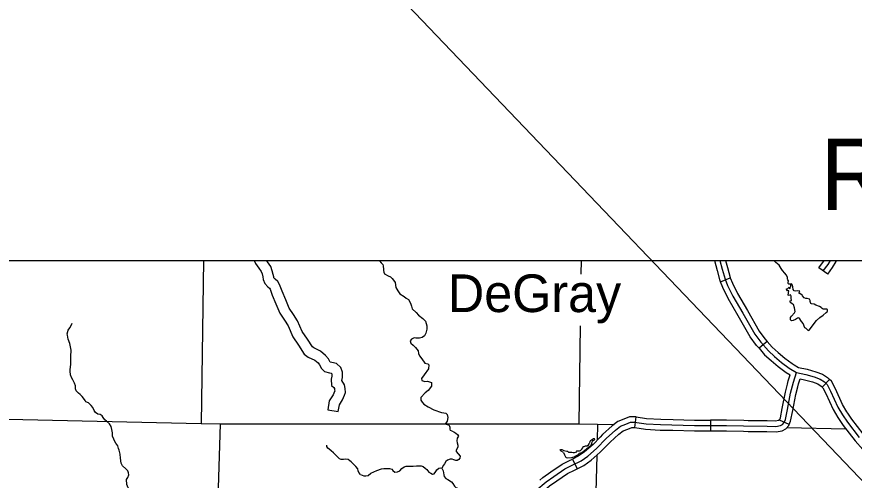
# Model space of a CAD drawing. Extents: x 813775 to 1157140, y 1757555 to 1979907.
# Drawn here: x 927663 to 951173, y 1874542 to 1887546 of the extents above; entities that cross this region are included whole.
import ezdxf

# ---------------------------------------------------------------- set-up
doc = ezdxf.new("R2010")
doc.units = 0
for name, color, linetype in [('Level 24', 7, 'Continuous'), ('Level 31', 7, 'Continuous'), ('Level 32', 7, 'Continuous'), ('Level 35', 7, 'Continuous'), ('Level 4', 7, 'Continuous'), ('Level 45', 7, 'Continuous'), ('Level 46', 7, 'Continuous'), ('Level 5', 7, 'Continuous'), ('R_Draft', 7, 'Continuous')]:
    doc.layers.add(name, color=color, linetype=linetype)

msp = doc.modelspace()

# ---------------------------------------------------------------- linework, layer by layer
at = {"layer": 'Level 31'}
for p, q in [((947416, 1880105), (947694, 1880218)), ((948729, 1878439), (948501, 1878244)), ((950480, 1877372), (950274, 1877154)), ((950994, 1876420), (950994, 1876420)), ((945009, 1876020), (945050, 1876317)), ((947138, 1876229), (947138, 1875929)), ((949348, 1876107), (949074, 1876229)), ((949074, 1876229), (949074, 1876229)), ((943263, 1875135), (943392, 1874864))]:
    msp.add_line(p, q, dxfattribs=at)
for points in [[(947249, 1880709), (947321, 1880429), (947404, 1880134), (947416, 1880105)], [(947404, 1880709), (947466, 1880468), (947546, 1880183), (947617, 1880009), (947764, 1879711), (948043, 1879226), (948381, 1878644), (948550, 1878418), (948763, 1878169), (948936, 1878013), (949131, 1877849), (949349, 1877689), (949555, 1877567)], [(947559, 1880709), (947611, 1880507), (947688, 1880232), (947694, 1880218)], [(947694, 1880218), (947754, 1880070), (947896, 1879781), (948173, 1879301)], [(947913, 1879151), (947631, 1879640), (947480, 1879947), (947416, 1880105)], [(948173, 1879301), (948173, 1879301), (948506, 1878727), (948667, 1878511), (948729, 1878439)], [(948501, 1878244), (948432, 1878324), (948255, 1878561), (947914, 1879151), (947913, 1879151)], [(948729, 1878439), (948870, 1878274), (949034, 1878126), (949224, 1877967), (949432, 1877814), (949486, 1877782)], [(948501, 1878244), (948655, 1878064), (948837, 1877900), (949038, 1877731), (949266, 1877563), (949375, 1877499)], [(949486, 1877782), (949611, 1877708), (949851, 1877654), (950097, 1877585), (950281, 1877515), (950426, 1877423), (950480, 1877372)], [(949555, 1877567), (949814, 1877509), (950049, 1877442), (950214, 1877380), (950334, 1877304), (950414, 1877229), (950507, 1877042), (950711, 1876593), (950840, 1876380), (950986, 1876167), (951311, 1875744)], [(949296, 1877233), (949322, 1877333), (949375, 1877499)], [(949587, 1877159), (949610, 1877250), (949656, 1877391)], [(949656, 1877391), (949777, 1877363), (950002, 1877299), (950147, 1877245), (950241, 1877185), (950274, 1877154)], [(950994, 1876420), (950966, 1876461), (950844, 1876663), (950642, 1877107), (950536, 1877319), (950480, 1877372)], [(949074, 1876229), (949100, 1876288), (949150, 1876551), (949240, 1877014), (949296, 1877233)], [(949348, 1876107), (949388, 1876198), (949445, 1876495), (949533, 1876948), (949587, 1877159)], [(950274, 1877154), (950291, 1877138), (950371, 1876977), (950578, 1876523), (950714, 1876299), (950747, 1876250)], [(951636, 1875608), (951426, 1875840), (951108, 1876255), (950994, 1876420)], [(945050, 1876317), (945016, 1876322), (944860, 1876316), (944708, 1876253), (944540, 1876189), (944375, 1876065), (944109, 1875822), (944042, 1875753)], [(945050, 1876317), (945343, 1876277), (945739, 1876251), (946085, 1876243)], [(946085, 1876243), (946693, 1876229), (947138, 1876229)], [(948196, 1876213), (948071, 1876215), (947590, 1876229), (947138, 1876229)], [(949074, 1876229), (949081, 1876246), (949060, 1876223), (949050, 1876217), (948962, 1876202), (948727, 1876206), (948196, 1876213)], [(950747, 1876250), (950865, 1876078), (951195, 1875648), (951413, 1875407)], [(944258, 1875544), (944318, 1875607), (944567, 1875834), (944686, 1875924), (944819, 1875975), (944925, 1876019), (945001, 1876021), (945009, 1876020)], [(945009, 1876020), (945313, 1875978), (945725, 1875951), (946078, 1875943)], [(946078, 1875943), (946689, 1875929), (947138, 1875929)], [(947138, 1875929), (947586, 1875929), (948064, 1875915), (948191, 1875913)], [(948191, 1875913), (948722, 1875906), (948985, 1875902), (949154, 1875931), (949250, 1875987), (949336, 1876079), (949348, 1876107)], [(944042, 1875753), (943840, 1875543), (943601, 1875339), (943426, 1875213), (943263, 1875135)], [(943392, 1874864), (943580, 1874953), (943787, 1875103), (944045, 1875325), (944258, 1875544)], [(942344, 1874542), (942430, 1874617), (942655, 1874773), (942974, 1874992), (943184, 1875098), (943263, 1875135)], [(942542, 1874316), (942615, 1874380), (942826, 1874526), (943127, 1874734), (943316, 1874828), (943392, 1874864)]]:
    msp.add_lwpolyline(points, dxfattribs=at)
at = {"layer": 'Level 32'}
msp.add_line((950427, 1880327), (950183, 1880503), dxfattribs=at)
for points in [[(950183, 1880503), (950313, 1880682), (950331, 1880709)], [(950305, 1880415), (950437, 1880597), (950510, 1880709)], [(950427, 1880327), (950560, 1880512), (950667, 1880675), (950678, 1880709)]]:
    msp.add_lwpolyline(points, dxfattribs=at)
at = {"layer": 'Level 35'}
for points in [[(937842, 1880709), (937850, 1880694), (937895, 1880644), (937937, 1880595), (937947, 1880558), (937955, 1880459), (937960, 1880423), (937963, 1880381), (937989, 1880329), (938090, 1880276), (938150, 1880245), (938200, 1880198), (938239, 1880157), (938288, 1880086), (938304, 1879951), (938356, 1879857), (938419, 1879771), (938539, 1879695), (938591, 1879650), (938659, 1879609), (938718, 1879512), (938742, 1879429), (938760, 1879350), (938875, 1879251), (938945, 1879173), (939058, 1879076), (939133, 1879003), (939170, 1878878), (939175, 1878776), (939144, 1878671), (939107, 1878595), (939042, 1878548), (938964, 1878530), (938870, 1878532), (938818, 1878535), (938742, 1878503), (938711, 1878449), (938721, 1878389), (938789, 1878331), (938852, 1878266), (938927, 1878169), (938943, 1878096), (938971, 1878031), (939031, 1877947), (939122, 1877824), (939207, 1877806), (939232, 1877782), (939224, 1877671), (939096, 1877503), (939028, 1877398), (939036, 1877336), (939120, 1877309), (939193, 1877320), (939305, 1877286), (939310, 1877177), (939211, 1877064), (939127, 1876991), (939010, 1876863), (939002, 1876787), (939041, 1876735), (939091, 1876675), (939209, 1876605), (939370, 1876521), (939589, 1876443), (939655, 1876435), (939704, 1876419), (939746, 1876389), (939764, 1876306), (939746, 1876201), (939709, 1876144), (939710, 1876142)], [(949298, 1880236), (949262, 1880307), (949220, 1880354), (949157, 1880427), (949118, 1880484), (949064, 1880578), (948975, 1880648), (948914, 1880709)], [(949395, 1880046), (949337, 1880045), (949322, 1880066), (949319, 1880092), (949324, 1880132), (949311, 1880160), (949296, 1880184), (949296, 1880207), (949298, 1880236)], [(949620, 1879101), (949577, 1879093), (949525, 1879056), (949455, 1879020), (949416, 1879012), (949384, 1879040), (949379, 1879106), (949408, 1879145), (949499, 1879239), (949510, 1879278), (949494, 1879375), (949463, 1879476), (949431, 1879487), (949392, 1879516), (949369, 1879552), (949379, 1879573), (949408, 1879589), (949405, 1879651), (949403, 1879704), (949384, 1879740), (949343, 1879724), (949319, 1879732), (949319, 1879758), (949327, 1879777), (949330, 1879797), (949335, 1879855), (949298, 1879855), (949270, 1879899), (949267, 1879915), (949304, 1879923), (949350, 1879957), (949369, 1879912), (949377, 1879962), (949392, 1879980), (949395, 1880046)], [(949620, 1879101), (949685, 1878999), (949742, 1878928), (949755, 1878873), (949776, 1878824), (949815, 1878811), (949852, 1878769), (949878, 1878746), (949909, 1878748), (949948, 1878798), (950024, 1878905), (950110, 1879022), (950206, 1879106), (950303, 1879176), (950386, 1879249), (950412, 1879268), (950422, 1879296), (950420, 1879330), (950404, 1879343), (950365, 1879346), (950331, 1879343), (950297, 1879346), (950269, 1879364), (950248, 1879390), (950196, 1879414), (950096, 1879458), (950044, 1879479), (949971, 1879492), (949950, 1879503), (949937, 1879560), (949935, 1879589), (949914, 1879620), (949851, 1879643), (949812, 1879638), (949768, 1879662), (949716, 1879714), (949708, 1879743), (949684, 1879756), (949645, 1879782), (949630, 1879784), (949627, 1879813), (949648, 1879844), (949632, 1879850), (949580, 1879852), (949530, 1879842), (949489, 1879860), (949460, 1879894), (949447, 1879972), (949442, 1880019), (949410, 1880048), (949395, 1880046)], [(929150, 1878382), (929104, 1878504), (929083, 1878608), (929080, 1878653), (929102, 1878751), (929155, 1878818), (929203, 1878903), (929221, 1878945)], [(929160, 1877653), (929179, 1877787), (929184, 1877909), (929181, 1878012), (929189, 1878191), (929150, 1878382)], [(929938, 1876394), (929872, 1876446), (929835, 1876499), (929800, 1876579), (929755, 1876643), (929673, 1876714), (929601, 1876746), (929585, 1876781), (929540, 1876847), (929497, 1876895), (929442, 1876946), (929397, 1876986), (929333, 1877049), (929312, 1877105), (929314, 1877193), (929280, 1877262), (929235, 1877360), (929203, 1877427), (929171, 1877501), (929158, 1877600), (929160, 1877653)], [(930353, 1875777), (930350, 1875875), (930334, 1875966), (930310, 1876048), (930268, 1876125), (930180, 1876197), (930132, 1876237), (930092, 1876301), (930060, 1876348), (930007, 1876388), (929938, 1876394)], [(939884, 1875923), (939842, 1875940), (939834, 1875974), (939834, 1876019), (939824, 1876050), (939811, 1876068), (939782, 1876092), (939751, 1876097), (939730, 1876110), (939706, 1876128), (939710, 1876142)], [(939884, 1875923), (939936, 1875899), (939986, 1875865), (940035, 1875828), (940059, 1875776), (940030, 1875726), (940019, 1875645), (940025, 1875593), (940043, 1875530), (940044, 1875496), (940046, 1875473), (939999, 1875383), (940001, 1875344), (940108, 1875217), (940098, 1875159), (940077, 1875127), (940022, 1875091), (939986, 1875094), (939931, 1875114), (939884, 1875133), (939826, 1875133), (939756, 1875107), (939709, 1875070), (939667, 1875002), (939644, 1874961), (939600, 1874880)], [(930384, 1875693), (930353, 1875777)], [(930597, 1875022), (930573, 1875159), (930562, 1875273), (930539, 1875385), (930517, 1875432), (930501, 1875507), (930446, 1875584), (930406, 1875648), (930384, 1875693)], [(943739, 1875491), (943778, 1875513), (943786, 1875523), (943805, 1875550), (943809, 1875572), (943810, 1875591), (943815, 1875610), (943826, 1875630), (943848, 1875652), (943877, 1875677), (943891, 1875689), (943881, 1875704), (943871, 1875708), (943851, 1875701), (943800, 1875663), (943769, 1875647), (943749, 1875625), (943741, 1875595), (943732, 1875562)], [(937313, 1874702), (937263, 1874762), (937250, 1874801), (937235, 1874858), (937185, 1874926), (937094, 1875015), (937052, 1875057), (937016, 1875088), (936966, 1875122), (936903, 1875130), (936836, 1875122), (936770, 1875125), (936726, 1875145), (936674, 1875190), (936606, 1875250), (936559, 1875307), (936489, 1875370), (936429, 1875409), (936397, 1875443), (936364, 1875487), (936364, 1875529)], [(943007, 1875320), (942950, 1875360), (942929, 1875376), (942917, 1875391), (942934, 1875404), (942967, 1875404), (943020, 1875378), (943102, 1875361), (943127, 1875356), (943155, 1875333), (943192, 1875331), (943242, 1875331), (943278, 1875322), (943320, 1875318), (943387, 1875337), (943375, 1875356), (943385, 1875367), (943405, 1875369), (943419, 1875365), (943441, 1875362), (943464, 1875365), (943492, 1875379), (943530, 1875414), (943550, 1875447), (943564, 1875484), (943587, 1875491), (943632, 1875503), (943674, 1875507), (943709, 1875536), (943732, 1875562)], [(943007, 1875320), (943042, 1875256), (943063, 1875196), (943085, 1875177), (943127, 1875173), (943246, 1875182), (943275, 1875186), (943315, 1875198), (943357, 1875229), (943409, 1875254), (943458, 1875297), (943524, 1875322), (943565, 1875346), (943647, 1875412), (943722, 1875476), (943739, 1875491)], [(930857, 1873675), (930969, 1873796), (931086, 1873892), (931176, 1873972), (931208, 1874025), (931224, 1874062), (931208, 1874113), (931144, 1874155), (931070, 1874190), (930950, 1874198), (930852, 1874261), (930788, 1874333), (930754, 1874426), (930748, 1874567), (930783, 1874618), (930809, 1874689), (930801, 1874748), (930778, 1874806), (930727, 1874865), (930631, 1874942), (930597, 1875022)], [(937313, 1874702), (937407, 1874663), (937464, 1874661), (937529, 1874679), (937602, 1874739), (937772, 1874812), (937900, 1874864), (937967, 1874867), (938048, 1874870), (938129, 1874872), (938194, 1874854), (938218, 1874817), (938278, 1874768), (938351, 1874773), (938416, 1874809), (938473, 1874867), (938536, 1874919), (938596, 1874935), (938651, 1874937), (938708, 1874937), (938789, 1874940), (938883, 1874945), (939011, 1874950), (939076, 1874930), (939131, 1874880), (939178, 1874841), (939227, 1874768), (939287, 1874742), (939331, 1874716), (939378, 1874723), (939428, 1874783), (939459, 1874838), (939511, 1874880), (939553, 1874890), (939600, 1874880), (939629, 1874804), (939650, 1874695), (939657, 1874650)], [(939657, 1874650), (939705, 1874595), (939762, 1874561), (939866, 1874501), (939903, 1874448), (939952, 1874378), (939992, 1874341), (940088, 1874297), (940169, 1874250), (940372, 1874075), (940432, 1874013), (940482, 1873921), (940602, 1873767), (940696, 1873693)]]:
    msp.add_lwpolyline(points, dxfattribs=at)
at = {"layer": 'Level 4'}
for points in [[(924074, 1876331), (932842, 1876138), (933375, 1876127), (943440, 1876127), (943967, 1876117), (944433, 1876108)], [(949278, 1876017), (950936, 1875986)]]:
    msp.add_lwpolyline(points, dxfattribs=at)
at = {"layer": 'Level 45'}
for points in [[(943051, 1874863), (943250, 1874963), (943503, 1875083), (943694, 1875221), (943942, 1875434), (944213, 1875714), (944471, 1875950), (944613, 1876056), (944764, 1876114), (944893, 1876167), (945008, 1876172), (945328, 1876127), (945732, 1876101), (946691, 1876079), (947588, 1876079), (948067, 1876065), (948725, 1876056), (948973, 1876052), (949102, 1876074), (949155, 1876105), (949209, 1876163), (949244, 1876243), (949297, 1876523), (949386, 1876981), (949466, 1877292), (949555, 1877567)], [(939789, 1873164), (940121, 1873325), (940538, 1873503), (940667, 1873530), (940960, 1873610), (941249, 1873663), (941466, 1873730), (941715, 1873859), (941924, 1874001), (942239, 1874250), (942523, 1874499), (942741, 1874650), (943051, 1874863)]]:
    msp.add_lwpolyline(points, dxfattribs=at)
at = {"layer": 'Level 46'}
for points in [[(934327, 1880709), (934363, 1880625), (934455, 1880492), (934526, 1880394), (934550, 1880329), (934571, 1880250), (934583, 1880171), (934624, 1880059), (934711, 1879972), (934758, 1879927), (934772, 1879904), (934837, 1879736), (934938, 1879489)], [(935216, 1879603), (935116, 1879847), (935043, 1880037), (934994, 1880116), (934921, 1880186), (934883, 1880225), (934875, 1880247), (934865, 1880311), (934837, 1880419), (934794, 1880537), (934700, 1880666), (934670, 1880709)], [(934939, 1879488), (935047, 1879233), (935179, 1879029), (935283, 1878875), (935413, 1878566), (935576, 1878332), (935735, 1878082), (935839, 1877997), (936027, 1877910), (936121, 1877833), (936163, 1877781), (936216, 1877677), (936301, 1877591), (936443, 1877552), (936495, 1877542), (936501, 1877536), (936510, 1877514), (936510, 1877463), (936487, 1877375), (936496, 1877199), (936562, 1877141), (936580, 1877112), (936587, 1877077), (936589, 1877042), (936587, 1877034), (936541, 1876939), (936437, 1876766), (936392, 1876520), (936687, 1876466)], [(936687, 1876466), (936722, 1876658), (936806, 1876797), (936867, 1876926), (936892, 1877007), (936885, 1877114), (936865, 1877223), (936793, 1877337), (936789, 1877341), (936789, 1877344), (936810, 1877425), (936810, 1877570), (936756, 1877709), (936637, 1877819), (936512, 1877845), (936460, 1877859), (936416, 1877946), (936334, 1878046), (936187, 1878166), (936000, 1878253), (935962, 1878284), (935826, 1878499), (935677, 1878711), (935548, 1879018), (935429, 1879195), (935312, 1879374), (935215, 1879605)]]:
    msp.add_lwpolyline(points, dxfattribs=at)
at = {"layer": 'Level 5'}
for points in [[(932903, 1880709), (932842, 1876138)], [(943503, 1880709), (943498, 1880323)], [(943478, 1878872), (943440, 1876127)], [(933375, 1876127), (933234, 1871615)], [(943967, 1876117), (943955, 1875662)], [(943943, 1875237), (943671, 1865382)]]:
    msp.add_lwpolyline(points, dxfattribs=at)
at = {"layer": 'R_Draft'}
msp.add_line((982982, 1841465), (928075, 1898928), dxfattribs=at)
msp.add_lwpolyline([(912532, 1880709), (1062535, 1880709), (1062535, 1798155), (912532, 1798155)], close=True, dxfattribs=at)

# ---------------------------------------------------------------- texts
at = {"layer": 'Level 24'}
msp.add_text('DeGray', height=1056, dxfattribs=at).set_placement((939766, 1879260))
at = {"layer": 'R_Draft'}
msp.add_text('R 20 W', height=2000, dxfattribs=at).set_placement((950215, 1882127))

doc.saveas('drawing.dxf')
